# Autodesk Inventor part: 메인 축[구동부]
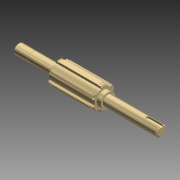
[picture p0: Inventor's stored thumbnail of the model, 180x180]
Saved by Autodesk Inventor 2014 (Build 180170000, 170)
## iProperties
Created: 2015-11
Part Number: 메인 축[구동부]
Document SubType Name: 모델링
Designer: mdu
Mass: 168.566 g
Surface Area: 72.5104 cm^2
Volume: 21.4461 cm^3
Density: 7.86 g/cm^3
Material: 강철, 연강
Appearance: 강철
변환 표준: STEP AP214IS
파일 이름: C:\Users\SeoGD\Desktop\?쒗뿕\硫붿씤 異?.stp
전처리기: Build: 253, Release: 2010 SP1 - Date: Wed 07/29/2009
전송 단위: 밀리미터
불확실성: 0.01
Author: mdu
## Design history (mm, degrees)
sketch "스케치1"
  geometry: L1 (-69.5, 0)-(69.5, 0); L2 (69.5, 0)-(69.5, 5); L3 (69.5, 5)-(55.5, 5); L4 (55.5, 5)-(55.5, 4.8); L5 (55.5, 4.8)-(54.35, 4.8); L6 (54.35, 4.8)-(54.35, 5); L7 (54.35, 5)-(30.5, 5); L8 (30.5, 5)-(30.5, 9); L9 (30.5, 9)-(-13.5, 9); L10 (-13.5, 9)-(-13.5, 7); L11 (-13.5, 7)-(-17.5, 7); L12 (-17.5, 7)-(-17.5, 5); L13 (-17.5, 5)-(-69.5, 5); L14 (-69.5, 5)-(-69.5, 0); 2 further points
  constraints: 28 end point, 9 parallel, 4 collinear, 2 perpendicular, 1 coincident, 1 horizontal, 1 midpoint
  dimensions: "d2" = 1.15 distance between parallel lines of L6 L4; "d3" = 10 diameter of L3 L1; "d4" = 9.6 diameter of L5 L1; "d6" = 44 distance between parallel lines of L10 L8; "d7" = 4 distance between parallel lines of L12 L10; "d8" = 14 diameter of L11 L1; "d9" = 18 diameter of L9 L1; "d33" = 52 distance from line of L12.end L14; "d37" = 39 distance between parallel lines of L8 L2; "d38" = 14 distance between parallel lines of L2 L4
revolve "회전1" sketch "스케치1" stored, may be unused: angle "d10" = 90 deg
sketch "스케치2"
  geometry: L1 (2.5, 10.712)-(2.5, 8.646); L2 (-2.5, 10.712)-(-2.5, 8.646); A1 r 9 centre (0, 0) between (2.5, 8.646) and (-2.5, 8.646) reference; A2 r 11 centre (0, 0) between (2.5, 10.712) and (-2.5, 10.712); 1 further point
  constraints: 4 end point, 4 point on circle, 2 parallel, 1 centre point, 1 coincident, 1 vertical
  dimensions: "d11" = 22 diameter of A2; "d12" = 5 distance between parallel lines of L1 L2
extrude "돌출1" join sketch "스케치2" stored distance "d13" = 10; taper "d14" = 0 deg
chamfer "모따기1" distance "d15" = 1; stored, may be unused: second distance "d16" = 2, angle "d17" = 45 deg
node "작업 평면1"
node "작업 평면2"
sketch "스케치3"
  geometry: L1 (2.5, 10.712)-(2.5, 10.198); L2 (-2.5, 10.712)-(-2.5, 10.198); A1 r 11 centre (0, 0) between (2.5, 10.712) and (-2.5, 10.712) reference; A2 r 10.5 centre (0, 0) between (2.5, 10.198) and (-2.5, 10.198); 1 further point
  constraints: 4 end point, 2 point on circle, 1 centre point, 1 coincident, 1 parallel, 1 vertical
  dimensions: "d19" = 21 diameter of A2
extrude "돌출2" cut sketch "스케치3" distance "d20" = 1.35; taper "d21" = 0 deg
node "작업 평면3"
sketch "스케치4"
  geometry: L1 (-26, -5)-(-26, 5) reference; L2 (-26, 1.5)-(-12.5, 1.5); L3 (-12.5, -1.5)-(-26, -1.5); A1 r 1.5 centre (-12.5, 0) between (-12.5, -1.5) and (-12.5, 1.5); 2 further points
  constraints: 4 end point, 2 perpendicular, 2 point on circle, 2 point on line, 2 tangent, 1 centre point, 1 horizontal alignment, 1 midpoint
  dimensions: "d25" = 3 distance between parallel lines of L3 L2; "d26" = 15 dimension on A1 L1
extrude "돌출3" cut sketch "스케치4" distance "d27" = 1.8; taper "d28" = 0 deg
chamfer "모따기2" distance "d29" = 1; stored, may be unused: second distance "d30" = 2, angle "d31" = 45 deg
node "솔리드1"
node "솔리드 본체"
node "곡면 본체"
mirror "대칭1"
pattern_circular "원형 패턴1" dims "d23" = 360 deg
node "솔리드2"
other parameters: "d18" = -1.65
